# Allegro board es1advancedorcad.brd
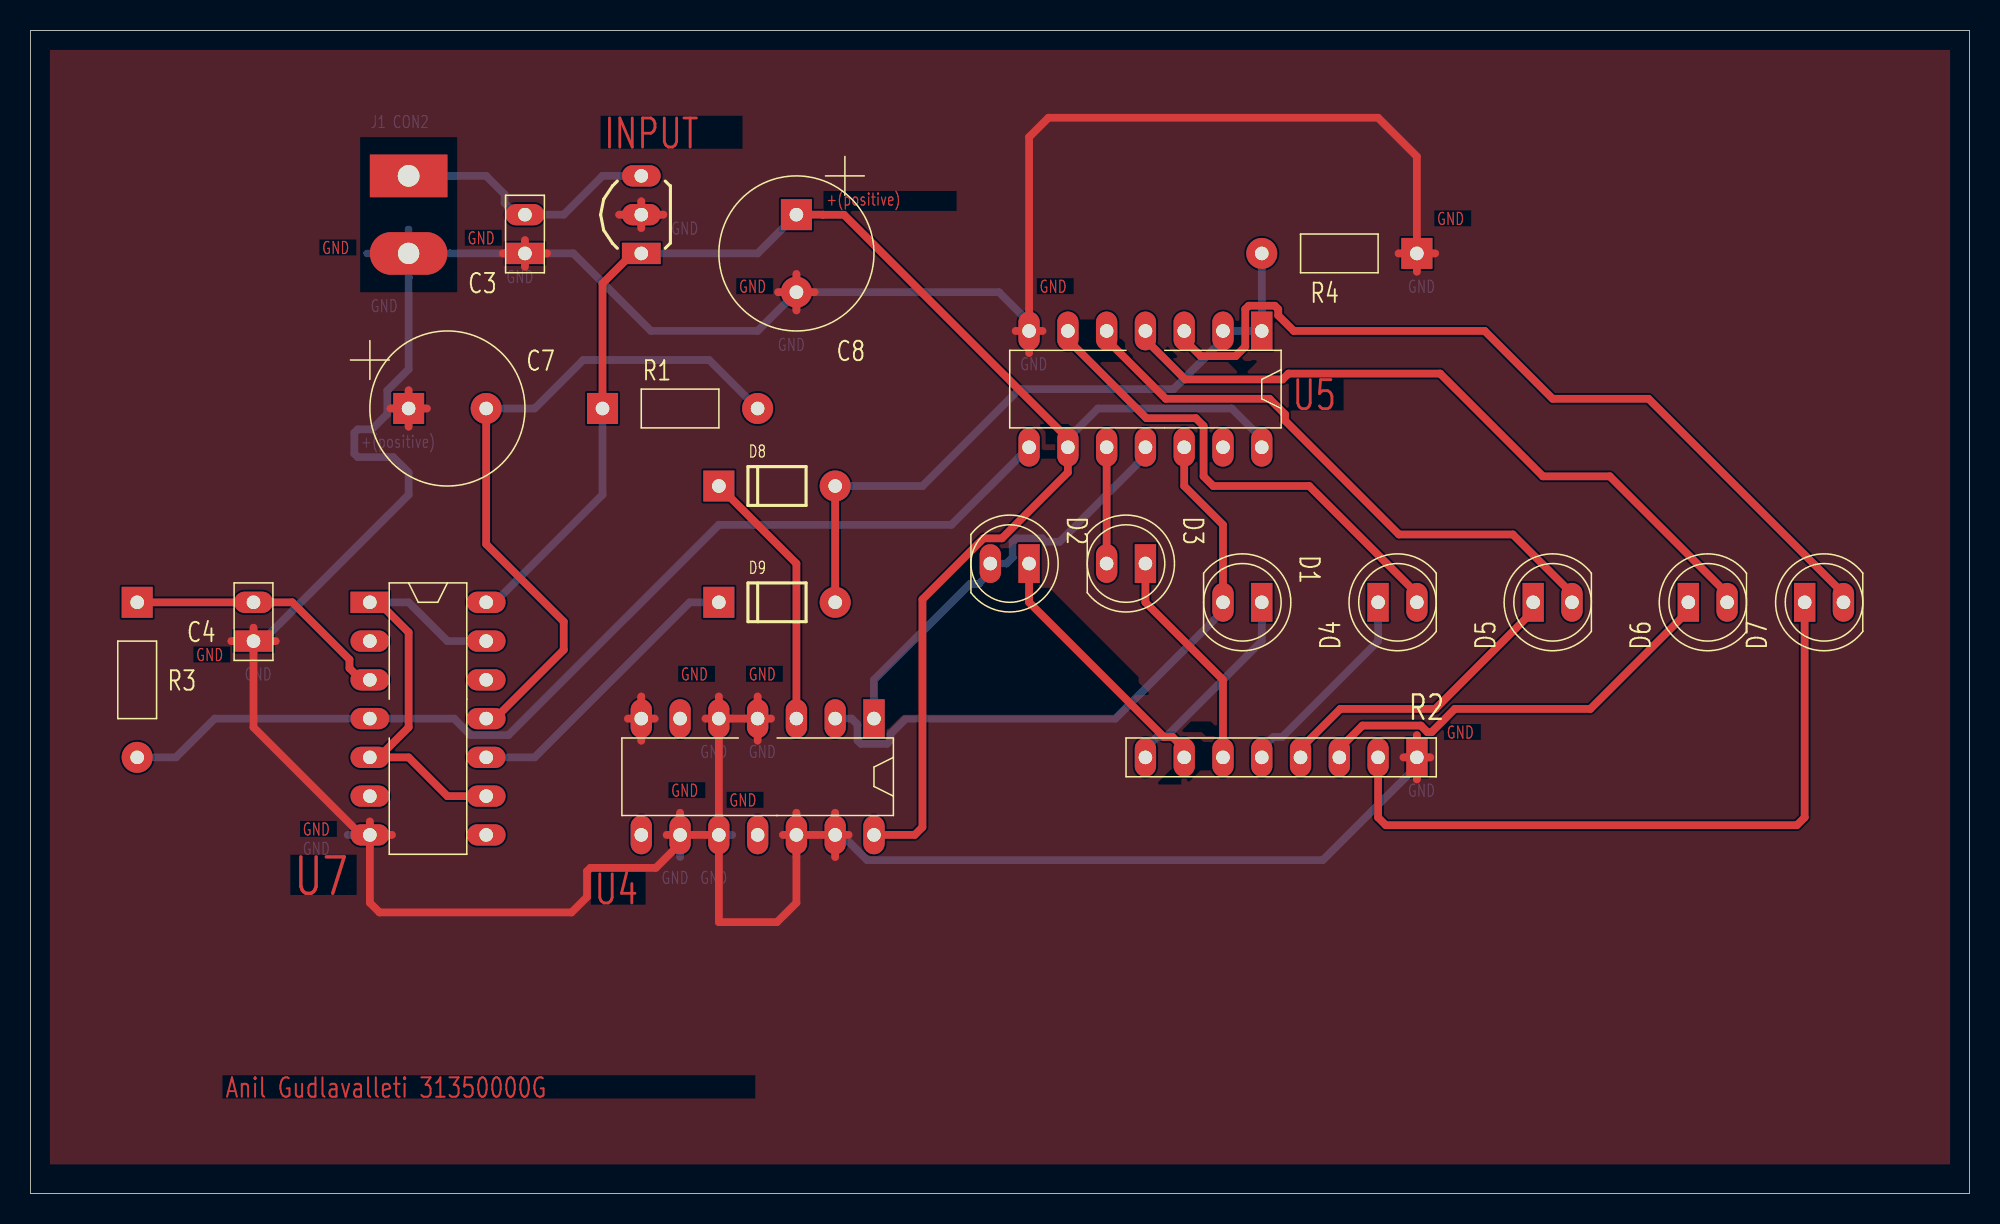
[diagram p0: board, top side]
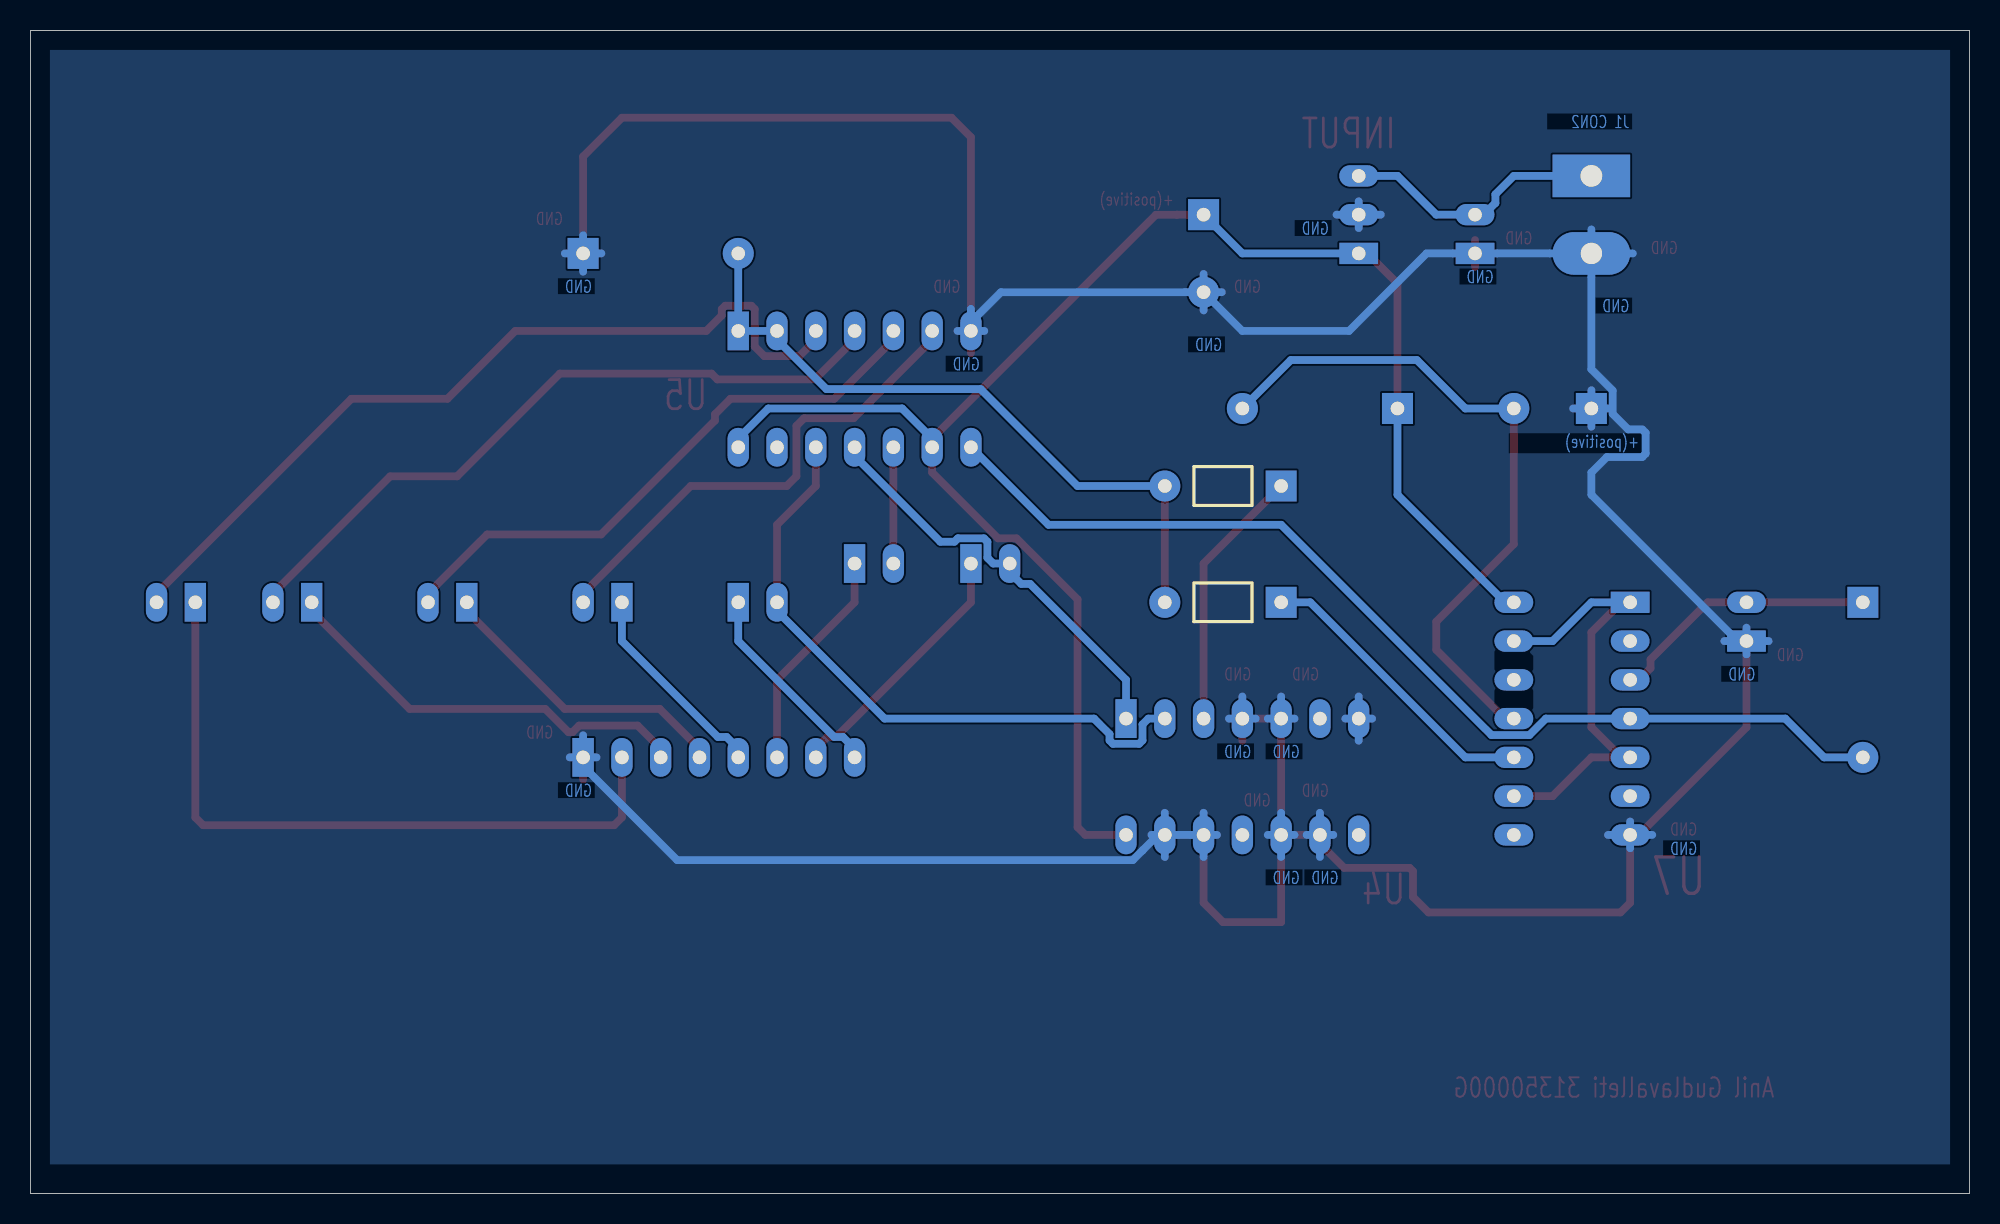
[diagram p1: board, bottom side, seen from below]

Outline 127 x 76.2 mm; copper layers: TOP, BOTTOM. Coordinates in mm from the lower left corner of the outline.
Outline path: 0,76.2 0,0 127,0 127,76.2 0,76.2

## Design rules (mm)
nets with their own width: min track width 0.508; nets GND N00877 N01443 N01455 N01467 N01471 N01483 N01495 N01507 N01519 N01531 N01543 N01547 N01559 N01571 N01583 N01856 N01860 N01925 N01931 N02144 N02493 N21662 VCC

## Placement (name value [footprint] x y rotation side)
C3  100n  [GU-RC100]  32.39 61.59 90 top
C4  220n  [GU-RC100]  14.61 36.19 90 top
C7  4u7  [GU-CAPCYL200]  24.77 51.44 0 top
C8  100u  [GU-CAPCYL200]  50.16 64.13 270 top
D1  LED  [GU-LED5MM]  80.65 38.74 270 top
D2  LED  [GU-LED5MM]  65.41 41.27 270 top
D3  LED  [GU-LED5MM]  73.03 41.27 270 top
D4  LED  [GU-LED5MM]  88.27 38.74 90 top
D5  LED  [GU-LED5MM]  98.42 38.74 90 top
D6  LED  [GU-LED5MM]  108.59 38.74 90 top
D7  LED  [GU-LED5MM]  116.21 38.74 90 top
D8  DIODE  [GU-1N4148]  45.09 46.35 0 top
D9  DIODE  [GU-1N4148]  45.09 38.74 0 top
J1  CON2  [GU-TERMINAL2-200]  24.77 66.68 0 top
R1  1M  [GU-RC400]  37.47 51.44 0 top
R2  330R  [GU-SIL8]  90.81 28.57 270 top
R3  2M2  [GU-RC400]  6.99 38.74 270 top
R4  100k  [GU-RC400]  90.81 61.59 180 top
U4  74HC86  [GU-DIP14]  55.25 31.12 270 top
U5  74HC164  [GU-DIP14]  80.65 56.51 270 top
U6  LM2931/TO92  [GU-TO92-100]  40.01 61.59 90 top
U7  74HC14  [GU-DIP14]  22.22 38.74 0 top

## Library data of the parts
C3 C4 = c
C7 C8 = C_elect_3
D1-D7 = LED
D8 D9 = DIODE
J1 = CON2: User Part Number: TERMINAL2-200
R1 R3 R4 = R
R2 = RESISTOR SIP 8_0
U4 = 74HC86
U5 = 74HC164
U6 = LM2931/TO92
U7 = 74HC14

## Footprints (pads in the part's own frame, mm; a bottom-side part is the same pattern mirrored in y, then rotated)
GU-1N4148
  round 2.032 hole 0.889: 1(7.62,0)
  rect 2.032x2.032 hole 0.889: 2(0,0)
GU-CAPCYL200
  rect 2.032x2.032 hole 0.889: 1(0,0)
  round 2.032 hole 0.889: 2(5.08,0)
GU-DIP14
  rect 2.54x1.397 hole 0.889: 1(0,0)
  oval 2.54x1.397 hole 0.889: 2(0,-2.54) 3(0,-5.08) 4(0,-7.62) 5(0,-10.16) 6(0,-12.7) 7(0,-15.24) 8(7.62,-15.24) 9(7.62,-12.7) 10(7.62,-10.16) 11(7.62,-7.62) 12(7.62,-5.08) 13(7.62,-2.54) 14(7.62,0)
GU-LED5MM
  rect 2.54x1.397 hole 0.889: 1(0,0)
  oval 2.54x1.397 hole 0.889: 2(0,-2.54)
GU-RC100
  rect 1.397x2.54 hole 0.889: 1(0,0)
  oval 1.397x2.54 hole 0.889: 2(2.54,0)
GU-RC400
  rect 2.032x2.032 hole 0.889: 1(0,0)
  round 2.032 hole 0.889: 2(10.16,0)
GU-SIL8
  rect 2.54x1.397 hole 0.889: 1(0,0)
  oval 2.54x1.397 hole 0.889: 2(0,-2.54) 3(0,-5.08) 4(0,-7.62) 5(0,-10.16) 6(0,-12.7) 7(0,-15.24) 8(0,-17.78)
GU-TERMINAL2-200
  rect 5.08x2.794 hole 1.422: 1(0,0)
  oval 5.08x2.794 hole 1.397: 2(0,-5.08)
GU-TO92-100
  rect 1.397x2.54 hole 0.889: 1(0,0)
  oval 1.397x2.54 hole 0.889: 2(2.54,0) 3(5.08,0)

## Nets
GND: C3.1 C4.1 C7.1 C8.2(-) J1.2 R2.1 R4.1 U4.4 U4.5 U4.7 U4.9 U4.10 U4.12 U4.13 U5.7 U6.2 U7.7
VCC: C8.1 R1.1 U4.14 U5.9 U5.14 U6.1(OUT) U7.14
N00877: C3.2 J1.1 U6.3
N01443: D1.2 U4.2 U5.12
N01455: D2.2 U4.1 U5.11
N01467: D3.2 U5.10
N01471: D4.2 U5.6
N01483: D5.2 U5.5
N01495: D6.2 U5.4
N01507: D7.2 U5.3
N01519: D1.1(CATHODE) R2.8
N01531: D2.1(CATHODE) R2.7
N01543: D3.1(CATHODE) R2.6
N01547: D4.1(CATHODE) R2.5
N01559: D5.1(CATHODE) R2.4
N01571: D6.1(CATHODE) R2.3
N01583: D7.1(CATHODE) R2.2
N01856: D8.2 U4.3
N01860: D8.1(K) D9.1(K) R4.2 U5.1 U5.2
N01925: D9.2 U7.10
N01931: C7.2(-) R1.2 U7.11
N02144: R3.2 U5.8 U7.4
N02493: C4.2 R3.1 U7.3
N21662: U7.1 U7.5 U7.9 U7.13

Pads without a net: U4 6 8 11; U5 13; U7 2 6 8 12

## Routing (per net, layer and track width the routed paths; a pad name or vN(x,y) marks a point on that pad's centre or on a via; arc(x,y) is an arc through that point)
GND: length 365.6
  TOP w0.508: C4.1 14.61,37.07 ; C4.1 13.16,36.19 ; C4.1 16.05,36.19 ; C4.1 14.61,30.54 21.65,23.49 U7.7 ; 39.13,31.12 U4.7 ; U4.7 40.01,29.67 ; U4.7 40.88,31.12 ; U4.7 40.01,32.56 ; U6.2 40.01,65.01 ; U6.2 40.01,63.26 ; U6.2 38.56,64.13 ; U6.2 41.45,64.13 ; U4.12 50.16,24.94 ; U4.12 51.63,23.49 ; U4.12 50.16,19.05 48.9,17.78 45.09,17.78 U4.10 ; U4.12 49.29,23.49 ; 41.67,23.49 U4.9 ; U4.9 42.54,24.94 ; U4.9 U4.10 ; U4.9 42.54,22.92 40.96,21.34 36.67,21.34 36.45,21.11 36.45,19.43 35.43,18.41 22.86,18.41 22.22,19.05 U7.7 ; 30.94,61.59 C3.1 ; C3.1 33.83,61.59 ; C3.1 32.39,60.72 ; C3.1 32.39,62.47 ; U4.5 U4.10 ; U4.5 44.21,31.12 ; U4.5 U4.4 ; U4.5 45.09,32.56 ; U7.7 22.22,24.37 ; U7.7 23.67,23.49 ; U4.4 47.63,32.56 ; U4.4 47.63,29.67 ; U4.4 48.5,31.12 ; U4.13 53.58,23.49 ; U4.13 51.83,23.49 ; U4.13 52.71,22.05 ; U4.13 52.71,24.94 ; 90.81,60.4 R4.1 ; R4.1 89.61,61.59 ; R4.1 92,61.59 ; R4.1 90.81,67.94 88.27,70.49 66.67,70.49 65.41,69.21 U5.7 ; 23.57,51.44 C7.1 ; C7.1 24.77,52.63 ; C7.1 24.77,50.24 ; C7.1 25.96,51.44 ; C8.2 50.16,60.25 ; C8.2 48.97,59.06 ; C8.2 50.16,57.86 ; C8.2 51.36,59.06 ; U5.7 66.28,56.51 ; U5.7 64.53,56.51 ; U5.7 65.41,55.07 ; R2.1 91.68,28.57 ; R2.1 90.81,27.13 ; R2.1 90.81,30.02 ; R2.1 89.93,28.57
  BOTTOM w0.508: 65.41,57.09 U5.7 ; 65.41,57.09 65.41,57.96 ; 65.41,57.09 63.44,59.06 C8.2 ; U5.7 66.28,56.51 ; U5.7 64.53,56.51 ; C8.2 50.16,60.25 ; C8.2 48.97,59.06 ; C8.2 50.16,57.86 ; C8.2 47.63,56.51 40.64,56.51 35.56,61.59 C3.1 J1.2 ; 22.22,22.62 U7.7 ; U7.7 20.78,23.49 ; U7.7 23.67,23.49 ; U7.7 22.22,24.37 ; 50.16,22.05 U4.12 ; U4.12 50.16,24.94 ; U4.12 49.29,23.49 ; U4.12 U4.13 ; U4.7 40.01,32.56 ; U4.7 39.13,31.12 ; U4.7 40.88,31.12 ; U4.7 40.01,29.67 ; R2.1 90.81,28 84.65,21.84 54.8,21.84 54.17,22.48 54.17,22.48 53.15,23.49 ; R2.1 91.68,28.57 ; R2.1 90.81,30.02 ; R2.1 89.93,28.57 ; 13.16,36.19 C4.1 ; C4.1 15.18,36.19 ; C4.1 14.61,37.07 ; C4.1 14.61,35.32 ; 90.81,60.4 R4.1 ; R4.1 92,61.59 ; R4.1 90.81,62.79 ; R4.1 89.61,61.59 ; 15.18,36.19 24.77,45.78 24.77,47.24 23.75,48.25 21.43,48.25 21.21,48.47 21.21,49.84 21.43,50.06 22.35,50.06 23.37,51.08 23.37,52.61 24.77,54.01 J1.2 ; 15.18,36.19 16.05,36.19 ; 24.77,50.24 C7.1 ; C7.1 23.57,51.44 ; C7.1 24.77,52.63 ; C7.1 25.96,51.44 ; U4.4 47.63,32.56 ; U4.4 48.5,31.12 ; U4.4 46.75,31.12 ; 40.01,63.26 U6.2 ; U6.2 38.56,64.13 ; U6.2 41.45,64.13 ; U6.2 40.01,65.01 ; U4.10 45.96,23.49 ; U4.10 44.21,23.49 ; U4.10 45.09,22.05 ; U4.10 45.09,24.94 ; U4.5 45.96,31.12 ; U4.5 44.21,31.12 ; U4.5 45.09,32.56 ; 22.05,61.59 J1.2 ; J1.2 24.77,63.17 ; 52.71,22.05 U4.13 ; U4.13 53.15,23.49 ; U4.13 52.71,24.94 ; U4.9 42.54,24.94 ; U4.9 41.67,23.49 ; U4.9 42.54,22.05 ; U4.9 43.42,23.49 ; 53.15,23.49 53.58,23.49
VCC: length 111.8
  TOP w0.508: U4.14 57.91,23.49 58.42,24 58.42,38.93 62.42,42.93 63.63,42.93 67.95,47.24 U5.9 67.95,49.47 53.28,64.13 51.91,64.13 51.9,64.13 C8.1 ; U6.1 39.43,61.59 37.47,59.63 R1.1
  BOTTOM w0.508: U6.1 47.63,61.59 C8.1 ; U5.9 67.95,49.47 69.91,51.44 78.68,51.44 80.65,49.47 U5.14 ; R1.1 37.47,45.78 30.42,38.74 U7.14
N00877: length 17.7
  BOTTOM w0.508: J1.1 29.84,66.68 31.05,65.47 31.05,64.9 31.81,64.13 C3.2 34.92,64.13 37.47,66.68 U6.3
N01443: length 42.3
  TOP w0.508: D1.2 78.1,43.81 75.57,46.35 U5.12
  BOTTOM w0.508: U4.2 53.78,31.12 54.17,30.73 54.17,29.69 54.39,29.46 56.1,29.46 56.32,29.69 56.32,30.1 57.34,31.12 71.06,31.12 78.1,38.16 D1.2
N01455: length 28.1
  BOTTOM w0.508: U4.1 55.25,33.65 61.53,39.94 62.1,39.94 62.87,40.7 D2.2 63.94,41.27 64.33,41.66 64.33,42.7 64.55,42.93 66.26,42.93 66.48,42.7 67.4,42.7 73.03,48.32 U5.11
N01467: length 7.6
  TOP w0.508: U5.10 D3.2
N01471: length 32.8
  TOP w0.508: D4.2 90.81,39.31 83.76,46.35 77.47,46.35 76.84,46.99 76.84,50.29 76.33,50.8 73.09,50.8 67.95,55.94 U5.6
N01483: length 38.8
  TOP w0.508: U5.5 70.48,55.94 74.36,52.07 81.15,52.07 82.17,51.05 82.17,50.64 89.63,43.18 97.09,43.18 100.97,39.31 D5.2
N01495: length 46.4
  TOP w0.508: D6.2 111.13,39.31 103.44,46.99 99.06,46.99 92.33,53.72 82.39,53.72 82.01,53.34 75.63,53.34 73.03,55.94 U5.4
N01507: length 55.6
  TOP w0.508: D7.2 118.75,39.31 105.98,52.07 99.7,52.07 95.25,56.51 82.74,56.51 81.72,57.53 81.72,57.94 81.5,58.17 79.79,58.17 79.57,57.94 79.57,55.5 78.93,54.86 76.64,54.86 75.57,55.94 U5.3
N01519: length 13.7
  BOTTOM w0.508: D1.1 80.65,36.19 74.36,29.91 73.79,29.91 73.03,29.15 R2.8
N01531: length 17.2
  TOP w0.508: R2.7 75.57,29.15 74.8,29.91 74.23,29.91 65.41,38.74 D2.1
N01543: length 14.8
  TOP w0.508: D3.1 73.03,38.74 78.1,33.65 R2.6
N01547: length 13.7
  BOTTOM w0.508: R2.5 80.65,29.15 81.41,29.91 81.98,29.91 88.27,36.19 D4.1
N01559: length 20.1
  TOP w0.508: D5.1 98.42,38.16 92.01,31.75 85.79,31.75 83.19,29.15 R2.4
N01571: length 28.1
  TOP w0.508: D6.1 108.59,38.16 102.17,31.75 93.29,31.75 91.76,30.23 91.5,30.23 91.07,30.66 87.24,30.66 85.72,29.15 R2.3
N01583: length 46.4
  TOP w0.508: R2.2 88.27,24.64 88.77,24.13 115.7,24.13 116.21,24.64 D7.1
N01856: length 17.3
  TOP w0.508: D8.2 50.16,41.27 U4.3
N01860: length 45.6
  TOP w0.508: 80.2,56.51 U5.1 ; D8.1 D9.1
  BOTTOM w0.508: D8.1 58.42,46.35 64.77,52.7 74.87,52.7 78.1,55.94 U5.2 U5.1 R4.2
N01925: length 19.4
  BOTTOM w0.508: D9.2 43.18,38.74 33.02,28.57 U7.10
N01931: length 45.3
  TOP w0.508: U7.11 30.42,31.12 34.92,35.62 34.92,37.46 29.84,42.55 C7.2
  BOTTOM w0.508: R1.2 44.45,54.61 36.2,54.61 33.02,51.44 C7.2
N02144: length 67.7
  BOTTOM w0.508: U5.8 60.33,43.81 45.09,43.81 31.31,30.04 28.83,30.04 27.75,31.12 U7.4 12.06,31.12 9.53,28.57 R3.2
N02493: length 17.7
  TOP w0.508: R3.1 C4.2 17.15,38.74 20.89,34.99 20.89,34.42 21.65,33.65 U7.3
N21662: length 29.7
  TOP w0.508: 22.8,28.57 24.77,28.57 27.31,26.03 U7.9 ; 22.8,28.57 U7.5 ; 22.8,28.57 24.77,30.54 24.77,36.77 22.8,38.74 U7.1
  BOTTOM w0.508: U7.13 27.31,36.19 24.77,38.74 U7.1

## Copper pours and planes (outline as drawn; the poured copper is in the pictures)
GND on TOP: 1.27,74.93 1.27,1.91 125.73,1.91 125.73,74.93 ; 10 cut-outs
GND on BOTTOM: 1.27,74.93 1.27,1.91 125.73,1.91 125.73,74.93 ; 2 cut-outs

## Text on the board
BOTTOM: GND | +(positive) | J1 CON2
TOP: GND | +(positive) | Anil Gudlavalleti 31350000G | U4 | INPUT | U5 | U7
